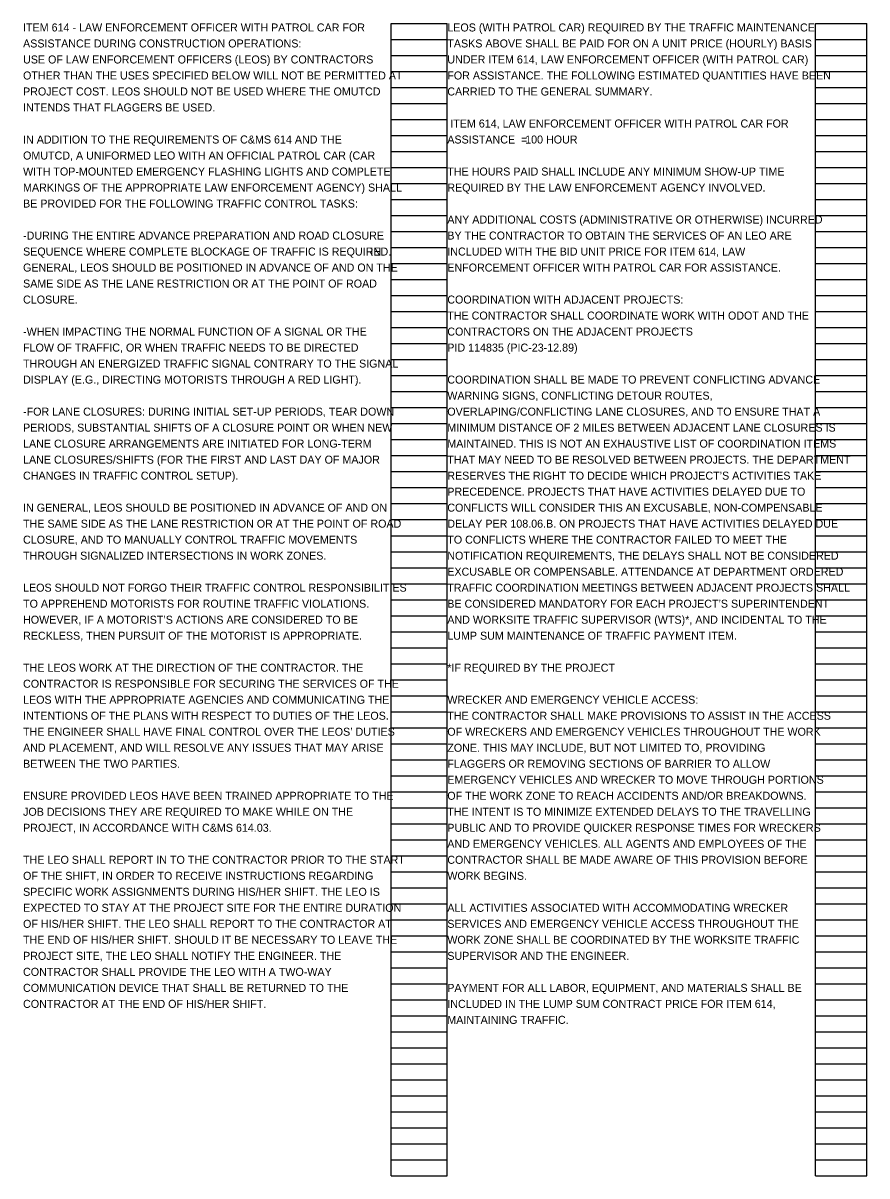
# Model space of a CAD drawing. Extents: x 24172 to 24226.9, y 11011.9 to 11091.2.
# Drawn here: x 24212.19 to 24226.95, y 11041.95 to 11062.11 of the extents above; entities that cross this region are included whole.
import ezdxf

# ---------------------------------------------------------------- set-up
doc = ezdxf.new("R2010")
doc.units = 0
doc.layers.add('SC_Scratch1', color=7, linetype='Continuous')
doc.layers.add('SH_Data', color=7, linetype='Continuous')

msp = doc.modelspace()

# ---------------------------------------------------------------- linework, layer by layer
at = {"layer": 'SH_Data'}
for p, q in [((24218.63, 11041.947), (24218.63, 11062.107)), ((24218.63, 11062.107), (24219.61, 11062.107)), ((24219.61, 11041.947), (24219.61, 11062.107)), ((24226.05, 11041.947), (24226.05, 11062.107)), ((24226.05, 11062.107), (24226.95, 11062.107)), ((24226.95, 11041.947), (24226.95, 11062.107)), ((24218.63, 11061.827), (24219.61, 11061.827)), ((24226.05, 11061.827), (24226.95, 11061.827)), ((24218.63, 11061.547), (24219.61, 11061.547)), ((24226.05, 11061.547), (24226.95, 11061.547)), ((24218.63, 11061.267), (24219.61, 11061.267)), ((24226.05, 11061.267), (24226.95, 11061.267)), ((24218.63, 11060.987), (24219.61, 11060.987)), ((24226.05, 11060.987), (24226.95, 11060.987)), ((24218.63, 11060.707), (24219.61, 11060.707)), ((24226.05, 11060.707), (24226.95, 11060.707)), ((24218.63, 11060.427), (24219.61, 11060.427)), ((24226.05, 11060.427), (24226.95, 11060.427)), ((24218.63, 11060.147), (24219.61, 11060.147)), ((24226.05, 11060.147), (24226.95, 11060.147)), ((24218.63, 11059.867), (24219.61, 11059.867)), ((24226.05, 11059.867), (24226.95, 11059.867)), ((24218.63, 11059.587), (24219.61, 11059.587)), ((24226.05, 11059.587), (24226.95, 11059.587)), ((24218.63, 11059.307), (24219.61, 11059.307)), ((24226.05, 11059.307), (24226.95, 11059.307)), ((24218.63, 11059.027), (24219.61, 11059.027)), ((24226.05, 11059.027), (24226.95, 11059.027)), ((24218.63, 11058.747), (24219.61, 11058.747)), ((24226.05, 11058.747), (24226.95, 11058.747)), ((24218.63, 11058.467), (24219.61, 11058.467)), ((24226.05, 11058.467), (24226.95, 11058.467)), ((24218.63, 11058.187), (24219.61, 11058.187)), ((24226.05, 11058.187), (24226.95, 11058.187)), ((24218.63, 11057.907), (24219.61, 11057.907)), ((24226.05, 11057.907), (24226.95, 11057.907)), ((24218.63, 11057.627), (24219.61, 11057.627)), ((24226.05, 11057.627), (24226.95, 11057.627)), ((24218.63, 11057.347), (24219.61, 11057.347)), ((24226.05, 11057.347), (24226.95, 11057.347)), ((24218.63, 11057.067), (24219.61, 11057.067)), ((24226.05, 11057.067), (24226.95, 11057.067)), ((24218.63, 11056.787), (24219.61, 11056.787)), ((24226.05, 11056.787), (24226.95, 11056.787)), ((24218.63, 11056.507), (24219.61, 11056.507)), ((24226.05, 11056.507), (24226.95, 11056.507)), ((24218.63, 11056.227), (24219.61, 11056.227)), ((24226.05, 11056.227), (24226.95, 11056.227)), ((24218.63, 11055.947), (24219.61, 11055.947)), ((24226.05, 11055.947), (24226.95, 11055.947)), ((24218.63, 11055.667), (24219.61, 11055.667)), ((24226.05, 11055.667), (24226.95, 11055.667)), ((24218.63, 11055.387), (24219.61, 11055.387)), ((24226.05, 11055.387), (24226.95, 11055.387)), ((24218.63, 11055.107), (24219.61, 11055.107)), ((24226.05, 11055.107), (24226.95, 11055.107)), ((24218.63, 11054.827), (24219.61, 11054.827)), ((24226.05, 11054.827), (24226.95, 11054.827)), ((24218.63, 11054.547), (24219.61, 11054.547)), ((24226.05, 11054.547), (24226.95, 11054.547)), ((24218.63, 11054.267), (24219.61, 11054.267)), ((24226.05, 11054.267), (24226.95, 11054.267)), ((24218.63, 11053.987), (24219.61, 11053.987)), ((24226.05, 11053.987), (24226.95, 11053.987)), ((24218.63, 11053.707), (24219.61, 11053.707)), ((24226.05, 11053.707), (24226.95, 11053.707)), ((24218.63, 11053.427), (24219.61, 11053.427)), ((24226.05, 11053.427), (24226.95, 11053.427)), ((24218.63, 11053.147), (24219.61, 11053.147)), ((24226.05, 11053.147), (24226.95, 11053.147)), ((24218.63, 11052.867), (24219.61, 11052.867)), ((24226.05, 11052.867), (24226.95, 11052.867)), ((24218.63, 11052.587), (24219.61, 11052.587)), ((24226.05, 11052.587), (24226.95, 11052.587)), ((24218.63, 11052.307), (24219.61, 11052.307)), ((24226.05, 11052.307), (24226.95, 11052.307)), ((24218.63, 11052.027), (24219.61, 11052.027)), ((24226.05, 11052.027), (24226.95, 11052.027)), ((24218.63, 11051.747), (24219.61, 11051.747)), ((24226.05, 11051.747), (24226.95, 11051.747)), ((24218.63, 11051.467), (24219.61, 11051.467)), ((24226.05, 11051.467), (24226.95, 11051.467)), ((24218.63, 11051.187), (24219.61, 11051.187)), ((24226.05, 11051.187), (24226.95, 11051.187)), ((24218.63, 11050.907), (24219.61, 11050.907)), ((24226.05, 11050.907), (24226.95, 11050.907)), ((24218.63, 11050.627), (24219.61, 11050.627)), ((24226.05, 11050.627), (24226.95, 11050.627)), ((24218.63, 11050.347), (24219.61, 11050.347)), ((24226.05, 11050.347), (24226.95, 11050.347)), ((24218.63, 11050.067), (24219.61, 11050.067)), ((24226.05, 11050.067), (24226.95, 11050.067)), ((24218.63, 11049.787), (24219.61, 11049.787)), ((24226.05, 11049.787), (24226.95, 11049.787)), ((24218.63, 11049.507), (24219.61, 11049.507)), ((24226.05, 11049.507), (24226.95, 11049.507)), ((24218.63, 11049.227), (24219.61, 11049.227)), ((24226.05, 11049.227), (24226.95, 11049.227)), ((24218.63, 11048.947), (24219.61, 11048.947)), ((24226.05, 11048.947), (24226.95, 11048.947)), ((24218.63, 11048.667), (24219.61, 11048.667)), ((24226.05, 11048.667), (24226.95, 11048.667)), ((24218.63, 11048.387), (24219.61, 11048.387)), ((24226.05, 11048.387), (24226.95, 11048.387)), ((24218.63, 11048.107), (24219.61, 11048.107)), ((24226.05, 11048.107), (24226.95, 11048.107)), ((24218.63, 11047.827), (24219.61, 11047.827)), ((24226.05, 11047.827), (24226.95, 11047.827)), ((24218.63, 11047.547), (24219.61, 11047.547)), ((24226.05, 11047.547), (24226.95, 11047.547)), ((24218.63, 11047.267), (24219.61, 11047.267)), ((24226.05, 11047.267), (24226.95, 11047.267)), ((24218.63, 11046.987), (24219.61, 11046.987)), ((24226.05, 11046.987), (24226.95, 11046.987)), ((24218.63, 11046.707), (24219.61, 11046.707)), ((24226.05, 11046.707), (24226.95, 11046.707)), ((24218.63, 11046.427), (24219.61, 11046.427)), ((24226.05, 11046.427), (24226.95, 11046.427)), ((24218.63, 11046.147), (24219.61, 11046.147)), ((24226.05, 11046.147), (24226.95, 11046.147)), ((24218.63, 11045.867), (24219.61, 11045.867)), ((24226.05, 11045.867), (24226.95, 11045.867)), ((24218.63, 11045.587), (24219.61, 11045.587)), ((24226.05, 11045.587), (24226.95, 11045.587)), ((24218.63, 11045.307), (24219.61, 11045.307)), ((24226.05, 11045.307), (24226.95, 11045.307)), ((24218.63, 11045.027), (24219.61, 11045.027)), ((24226.05, 11045.027), (24226.95, 11045.027)), ((24218.63, 11044.747), (24219.61, 11044.747)), ((24226.05, 11044.747), (24226.95, 11044.747)), ((24218.63, 11044.467), (24219.61, 11044.467)), ((24226.05, 11044.467), (24226.95, 11044.467)), ((24218.63, 11044.187), (24219.61, 11044.187)), ((24226.05, 11044.187), (24226.95, 11044.187)), ((24218.63, 11043.907), (24219.61, 11043.907)), ((24226.05, 11043.907), (24226.95, 11043.907)), ((24218.63, 11043.627), (24219.61, 11043.627)), ((24226.05, 11043.627), (24226.95, 11043.627)), ((24218.63, 11043.347), (24219.61, 11043.347)), ((24226.05, 11043.347), (24226.95, 11043.347)), ((24218.63, 11043.067), (24219.61, 11043.067)), ((24226.05, 11043.067), (24226.95, 11043.067)), ((24218.63, 11042.787), (24219.61, 11042.787)), ((24226.05, 11042.787), (24226.95, 11042.787)), ((24218.63, 11042.507), (24219.61, 11042.507)), ((24226.05, 11042.507), (24226.95, 11042.507)), ((24218.63, 11042.227), (24219.61, 11042.227)), ((24226.05, 11042.227), (24226.95, 11042.227)), ((24218.63, 11041.947), (24219.61, 11041.947)), ((24226.05, 11041.947), (24226.95, 11041.947))]:
    msp.add_line(p, q, dxfattribs=at)

# ---------------------------------------------------------------- texts
at = {"layer": 'SC_Scratch1'}
for s, p in [('ITEM 614 - LAW ENFORCEMENT OFFICER WITH PATROL CAR FOR ', (24212.19, 11061.967)), ('ASSISTANCE DURING CONSTRUCTION OPERATIONS:', (24212.19, 11061.687)), ('USE OF LAW ENFORCEMENT OFFICERS (LEOS) BY CONTRACTORS ', (24212.19, 11061.407)), ('OTHER THAN THE USES SPECIFIED BELOW WILL NOT BE PERMITTED AT ', (24212.19, 11061.127)), ('PROJECT COST. LEOS SHOULD NOT BE USED WHERE THE OMUTCD ', (24212.19, 11060.847)), ('INTENDS THAT FLAGGERS BE USED.', (24212.19, 11060.567)), ('IN ADDITION TO THE REQUIREMENTS OF C&MS 614 AND THE ', (24212.19, 11060.007)), ('100 HOUR', (24220.972, 11060.007)), ('OMUTCD, A UNIFORMED LEO WITH AN OFFICIAL PATROL CAR (CAR ', (24212.19, 11059.727)), ('WITH TOP-MOUNTED EMERGENCY FLASHING LIGHTS AND COMPLETE ', (24212.19, 11059.447)), ('MARKINGS OF THE APPROPRIATE LAW ENFORCEMENT AGENCY) SHALL ', (24212.19, 11059.167)), ('BE PROVIDED FOR THE FOLLOWING TRAFFIC CONTROL TASKS:', (24212.19, 11058.887)), ('-DURING THE ENTIRE ADVANCE PREPARATION AND ROAD CLOSURE ', (24212.19, 11058.327)), ('SEQUENCE WHERE COMPLETE BLOCKAGE OF TRAFFIC IS REQUIRED.', (24212.19, 11058.047)), ('\xa0IN ', (24218.213, 11058.047)), ('GENERAL, LEOS SHOULD BE POSITIONED IN ADVANCE OF AND ON THE ', (24212.19, 11057.767)), ('SAME SIDE AS THE LANE RESTRICTION OR AT THE POINT OF ROAD ', (24212.19, 11057.487)), ('CLOSURE. ', (24212.19, 11057.207)), ('COORDINATION WITH ADJACENT PROJECTS:', (24219.61, 11057.207)), ('THE CONTRACTOR SHALL COORDINATE WORK WITH ODOT AND THE ', (24219.61, 11056.927)), ('-WHEN IMPACTING THE NORMAL FUNCTION OF A SIGNAL OR THE ', (24212.19, 11056.647)), ('CONTRACTORS ON THE ADJACENT PROJECTS', (24219.61, 11056.647)), (': ', (24223.57, 11056.647)), ('FLOW OF TRAFFIC, OR WHEN TRAFFIC NEEDS TO BE DIRECTED ', (24212.19, 11056.367)), ('PID 114835 (PIC-23-12.89)', (24219.61, 11056.367)), ('THROUGH AN ENERGIZED TRAFFIC SIGNAL CONTRARY TO THE SIGNAL ', (24212.19, 11056.087)), ('DISPLAY (E.G., DIRECTING MOTORISTS THROUGH A RED LIGHT). ', (24212.19, 11055.807)), ('COORDINATION SHALL BE MADE TO PREVENT CONFLICTING ADVANCE ', (24219.61, 11055.807)), ('WARNING SIGNS, CONFLICTING DETOUR ROUTES, ', (24219.61, 11055.527)), ('OVERLAPING/CONFLICTING LANE CLOSURES, AND TO ENSURE THAT A ', (24219.61, 11055.247)), ('-FOR LANE CLOSURES: DURING INITIAL SET-UP PERIODS, TEAR DOWN ', (24212.19, 11055.247)), ('PERIODS, SUBSTANTIAL SHIFTS OF A CLOSURE POINT OR WHEN NEW ', (24212.19, 11054.967)), ('MINIMUM DISTANCE OF 2 MILES BETWEEN ADJACENT LANE CLOSURES IS ', (24219.61, 11054.967)), ('LANE CLOSURE ARRANGEMENTS ARE INITIATED FOR LONG-TERM ', (24212.19, 11054.687)), ('MAINTAINED. THIS IS NOT AN EXHAUSTIVE LIST OF COORDINATION ITEMS ', (24219.61, 11054.687)), ('LANE CLOSURES/SHIFTS (FOR THE FIRST AND LAST DAY OF MAJOR ', (24212.19, 11054.407)), ('THAT MAY NEED TO BE RESOLVED BETWEEN PROJECTS. THE DEPARTMENT ', (24219.61, 11054.407)), ('CHANGES IN TRAFFIC CONTROL SETUP).', (24212.19, 11054.127)), ('RESERVES THE RIGHT TO DECIDE WHICH PROJECT’S ACTIVITIES TAKE ', (24219.61, 11054.127)), ('PRECEDENCE. PROJECTS THAT HAVE ACTIVITIES DELAYED DUE TO ', (24219.61, 11053.847)), ('IN GENERAL, LEOS SHOULD BE POSITIONED IN ADVANCE OF AND ON ', (24212.19, 11053.567)), ('CONFLICTS WILL CONSIDER THIS AN EXCUSABLE, NON-COMPENSABLE ', (24219.61, 11053.567)), ('THE SAME SIDE AS THE LANE RESTRICTION OR AT THE POINT OF ROAD ', (24212.19, 11053.287)), ('DELAY PER 108.06.B. ON PROJECTS THAT HAVE ACTIVITIES DELAYED DUE ', (24219.61, 11053.287)), ('CLOSURE, AND TO MANUALLY CONTROL TRAFFIC MOVEMENTS ', (24212.19, 11053.007)), ('TO CONFLICTS WHERE THE CONTRACTOR FAILED TO MEET THE ', (24219.61, 11053.007)), ('THROUGH SIGNALIZED INTERSECTIONS IN WORK ZONES. ', (24212.19, 11052.727)), ('NOTIFICATION REQUIREMENTS, THE DELAYS SHALL NOT BE CONSIDERED ', (24219.61, 11052.727)), ('EXCUSABLE OR COMPENSABLE. ATTENDANCE AT DEPARTMENT ORDERED ', (24219.61, 11052.447)), ('LEOS SHOULD NOT FORGO THEIR TRAFFIC CONTROL RESPONSIBILITIES ', (24212.19, 11052.167)), ('TRAFFIC COORDINATION MEETINGS BETWEEN ADJACENT PROJECTS SHALL ', (24219.61, 11052.167)), ('TO APPREHEND MOTORISTS FOR ROUTINE TRAFFIC VIOLATIONS. ', (24212.19, 11051.887)), ('BE CONSIDERED MANDATORY FOR EACH PROJECT’S SUPERINTENDENT ', (24219.61, 11051.887)), ('HOWEVER, IF A MOTORIST’S ACTIONS ARE CONSIDERED TO BE ', (24212.19, 11051.607)), ('AND WORKSITE TRAFFIC SUPERVISOR (WTS)*, AND INCIDENTAL TO THE ', (24219.61, 11051.607)), ('RECKLESS, THEN PURSUIT OF THE MOTORIST IS APPROPRIATE. ', (24212.19, 11051.327)), ('LUMP SUM MAINTENANCE OF TRAFFIC PAYMENT ITEM.', (24219.61, 11051.327)), ('THE LEOS WORK AT THE DIRECTION OF THE CONTRACTOR. THE ', (24212.19, 11050.767)), ('*IF REQUIRED BY THE PROJECT', (24219.61, 11050.767)), ('CONTRACTOR IS RESPONSIBLE FOR SECURING THE SERVICES OF THE ', (24212.19, 11050.487)), ('LEOS WITH THE APPROPRIATE AGENCIES AND COMMUNICATING THE ', (24212.19, 11050.207)), ('WRECKER AND EMERGENCY VEHICLE ACCESS:', (24219.61, 11050.207)), ('INTENTIONS OF THE PLANS WITH RESPECT TO DUTIES OF THE LEOS. ', (24212.19, 11049.927)), ('THE CONTRACTOR SHALL MAKE PROVISIONS TO ASSIST IN THE ACCESS ', (24219.61, 11049.927)), ('THE ENGINEER SHALL HAVE FINAL CONTROL OVER THE LEOS’ DUTIES ', (24212.19, 11049.647)), ('OF WRECKERS AND EMERGENCY VEHICLES THROUGHOUT THE WORK ', (24219.61, 11049.647)), ('AND PLACEMENT, AND WILL RESOLVE ANY ISSUES THAT MAY ARISE ', (24212.19, 11049.367)), ('ZONE. THIS MAY INCLUDE, BUT NOT LIMITED TO, PROVIDING ', (24219.61, 11049.367)), ('BETWEEN THE TWO PARTIES. ', (24212.19, 11049.087)), ('FLAGGERS OR REMOVING SECTIONS OF BARRIER TO ALLOW ', (24219.61, 11049.087)), ('EMERGENCY VEHICLES AND WRECKER TO MOVE THROUGH PORTIONS ', (24219.61, 11048.807)), ('ENSURE PROVIDED LEOS HAVE BEEN TRAINED APPROPRIATE TO THE ', (24212.19, 11048.527)), ('OF THE WORK ZONE TO REACH ACCIDENTS AND/OR BREAKDOWNS. ', (24219.61, 11048.527)), ('JOB DECISIONS THEY ARE REQUIRED TO MAKE WHILE ON THE ', (24212.19, 11048.247)), ('THE INTENT IS TO MINIMIZE EXTENDED DELAYS TO THE TRAVELLING ', (24219.61, 11048.247)), ('PROJECT, IN ACCORDANCE WITH C&MS 614.03. ', (24212.19, 11047.967)), ('PUBLIC AND TO PROVIDE QUICKER RESPONSE TIMES FOR WRECKERS ', (24219.61, 11047.967)), ('AND EMERGENCY VEHICLES. ALL AGENTS AND EMPLOYEES OF THE ', (24219.61, 11047.687)), ('THE LEO SHALL REPORT IN TO THE CONTRACTOR PRIOR TO THE START ', (24212.19, 11047.407)), ('CONTRACTOR SHALL BE MADE AWARE OF THIS PROVISION BEFORE ', (24219.61, 11047.407)), ('OF THE SHIFT, IN ORDER TO RECEIVE INSTRUCTIONS REGARDING ', (24212.19, 11047.127)), ('WORK BEGINS.', (24219.61, 11047.127)), ('SPECIFIC WORK ASSIGNMENTS DURING HIS/HER SHIFT. THE LEO IS ', (24212.19, 11046.847)), ('EXPECTED TO STAY AT THE PROJECT SITE FOR THE ENTIRE DURATION ', (24212.19, 11046.567)), ('ALL ACTIVITIES ASSOCIATED WITH ACCOMMODATING WRECKER ', (24219.61, 11046.567)), ('OF HIS/HER SHIFT. THE LEO SHALL REPORT TO THE CONTRACTOR AT ', (24212.19, 11046.287)), ('SERVICES AND EMERGENCY VEHICLE ACCESS THROUGHOUT THE ', (24219.61, 11046.287)), ('THE END OF HIS/HER SHIFT. SHOULD IT BE NECESSARY TO LEAVE THE ', (24212.19, 11046.007)), ('WORK ZONE SHALL BE COORDINATED BY THE WORKSITE TRAFFIC ', (24219.61, 11046.007)), ('PROJECT SITE, THE LEO SHALL NOTIFY THE ENGINEER. THE ', (24212.19, 11045.727)), ('SUPERVISOR AND THE ENGINEER.', (24219.61, 11045.727)), ('CONTRACTOR SHALL PROVIDE THE LEO WITH A TWO-WAY ', (24212.19, 11045.447)), ('COMMUNICATION DEVICE THAT SHALL BE RETURNED TO THE ', (24212.19, 11045.167)), ('PAYMENT FOR ALL LABOR, EQUIPMENT, AND MATERIALS SHALL BE ', (24219.61, 11045.167)), ('CONTRACTOR AT THE END OF HIS/HER SHIFT.', (24212.19, 11044.887)), ('INCLUDED IN THE LUMP SUM CONTRACT PRICE FOR ITEM 614, ', (24219.61, 11044.887)), ('MAINTAINING TRAFFIC.', (24219.61, 11044.607))]:
    msp.add_text(s, height=0.14, dxfattribs=at).set_placement(p)
at = {"layer": 'SH_Data'}
for s, p in [('LEOS (WITH PATROL CAR) REQUIRED BY THE TRAFFIC MAINTENANCE ', (24219.61, 11061.967)), ('TASKS ABOVE SHALL BE PAID FOR ON A UNIT PRICE (HOURLY) BASIS ', (24219.61, 11061.687)), ('UNDER ITEM 614, LAW ENFORCEMENT OFFICER (WITH PATROL CAR) ', (24219.61, 11061.407)), ('FOR ASSISTANCE. THE FOLLOWING ESTIMATED QUANTITIES HAVE BEEN ', (24219.61, 11061.127)), ('CARRIED TO THE GENERAL SUMMARY.', (24219.61, 11060.847)), (' ITEM 614, LAW ENFORCEMENT OFFICER WITH PATROL CAR FOR ', (24219.61, 11060.287)), ('ASSISTANCE  = ', (24219.61, 11060.007)), ('THE HOURS PAID SHALL INCLUDE ANY MINIMUM SHOW-UP TIME ', (24219.61, 11059.447)), ('REQUIRED BY THE LAW ENFORCEMENT AGENCY INVOLVED. ', (24219.61, 11059.167)), ('ANY ADDITIONAL COSTS (ADMINISTRATIVE OR OTHERWISE) INCURRED ', (24219.61, 11058.607)), ('BY THE CONTRACTOR TO OBTAIN THE SERVICES OF AN LEO ARE ', (24219.61, 11058.327)), ('INCLUDED WITH THE BID UNIT PRICE FOR ITEM 614, LAW ', (24219.61, 11058.047)), ('ENFORCEMENT OFFICER WITH PATROL CAR FOR ASSISTANCE.', (24219.61, 11057.767))]:
    msp.add_text(s, height=0.14, dxfattribs=at).set_placement(p)

doc.saveas('drawing.dxf')
